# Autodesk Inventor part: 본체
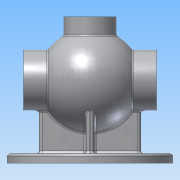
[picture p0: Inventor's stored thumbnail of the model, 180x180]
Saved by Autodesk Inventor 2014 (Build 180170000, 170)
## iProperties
Created: 2020-08
Part Number: 본체
Material: 알루미늄 6061
Document SubType Name: Modeling
Designer: kb542
Mass: 1759.43 g
Surface Area: 1343.08 cm^2
Volume: 649.236 cm^3
Density: 2.71 g/cm^3
Appearance: 알루미늄 - 평지
Author: kb542
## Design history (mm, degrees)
sketch "스케치1"
  geometry: L1 (-68, 0)-(68, 0); L2 (-68, 0)-(-68, 31); L3 (-68, 31)-(-42.988, 31); L4 (42.988, 31)-(68, 31); L5 (68, 31)-(68, 0); L6 (-52, 17.5)-(-52, 18.5); L7 (-52, 18.5)-(-50.25, 18.5); L8 (-50.25, 18.5)-(-50.25, 17.5); L9 (-50.25, 17.5)-(-39.278, 17.5); L10 (39.278, 17.5)-(68, 17.5); L11 (-52, 17.5)-(-68, 17.5); A1 r 43 centre (0, 0) between (39.278, 17.5) and (-39.278, 17.5); A2 r 53 centre (0, 0) between (42.988, 31) and (-42.988, 31); 2 further points
  constraints: 22 end point, 4 horizontal, 4 perpendicular, 4 point on circle, 3 coincident, 2 centre point, 2 point on line, 1 midpoint, 1 parallel, 1 vertical
  dimensions: "d0" = 136 distance of L1.start L1.end; "d1" = 62 diameter of L3 L1; "d2" = 62 diameter of L4 L1; "d8" = 35 diameter of L11 L1; "d9" = 37 diameter of L7 L1; "d10" = 1.75 distance of L6.end L7.end; "d11" = 35 diameter of L9 L1; "d12" = 43 radius of A1; "d13" = 35 diameter of L10 L1; "d14" = 16 distance of L6.start L11.end; "d16" = 53 radius of A2
revolve "회전1" sketch "스케치1" stored, may be unused: angle "d15" = 90 deg
chamfer "모따기1" distance "d17" = 1; stored, may be unused: second distance "d18" = 2, angle "d19" = 45 deg
sketch "스케치2"
  geometry: L1 (-27, 45.607)-(27, 45.607); L2 (-27, 45.607)-(27, 45.607); A1 r 53 centre (0, 0) between (-27, 45.607) and (27, 45.607) reference; A2 r 53 centre (0, 0) between (27, 45.607) and (-27, 45.607); 1 further point
  constraints: 4 end point, 4 point on circle, 2 horizontal, 1 centre point, 1 concentric
  dimensions: "d20" = 54 distance of L1.start L1.end; "d21" = 45.60702 distance from line of A2.centre L1
extrude "돌출1" cut sketch "스케치2" stored distance "d22" = 10; taper "d23" = 0 deg
sketch "스케치3"
  geometry: 2 further points
  constraints: 1 horizontal alignment
  dimensions: "d24" = 24 distance of point (0, 0) point (-24, 0)
hole "구멍1" sketch "스케치3" at (-24, 0) diameter "d25" = 3.242; stored, may be unused: countersink angle "d29" = 90 deg, drill point angle "d31" = 118 deg; dims "d26" = 12, "d27" = 4, "d28" = 2, "d30" = 15
sketch "스케치4"
  geometry: 2 further points
  constraints: 1 horizontal alignment
  dimensions: "d35" = 24 distance of point (0, 0) point (24, 0)
hole "구멍2" sketch "스케치4" at (24, 0) diameter "d36" = 3.242; stored, may be unused: countersink angle "d40" = 90 deg, drill point angle "d42" = 118 deg; dims "d37" = 12, "d38" = 4, "d39" = 2, "d41" = 15
node "작업 평면1"
sketch "스케치6"
  geometry: C1 r 85 at (0, 0); 1 further point
  constraints: 1 centre point, 1 coincident
  dimensions: "d47" = 170 diameter of C1
extrude "돌출2" join sketch "스케치6" distance "d48" = 10; taper "d49" = 0 deg
fillet "모깎기1" dims "d50" = 3
sketch "스케치7"
  geometry: A1 r 72.5 centre (0, 0) between (0, -72.5) and (72.5, 0); 3 further points
  constraints: 4 point on circle, 2 horizontal alignment, 2 vertical alignment, 1 centre point, 1 coincident
  dimensions: "d51" = 145 diameter of A1
hole "구멍3" sketch "스케치7" at (0, -72.5), (72.5, 0), (0, 72.5), (-72.5, 0) diameter "d52" = 9; stored, may be unused: countersink angle "d56" = 90 deg, drill point angle "d58" = 118 deg; dims "d53" = 12, "d54" = 4, "d55" = 2, "d57" = 15
sketch "스케치8"
  geometry: L1 (-82, -75)-(82, -75) reference; L2 (43, 0)-(43, -75); L3 (-43, 0)-(-43, -75); L4 (43, -75)-(-43, -75); A1 r 43 centre (0, 0) between (43, 0) and (-43, 0) reference; A2 r 43 centre (0, 0) between (-43, 0) and (43, 0); 1 further point
  constraints: 6 end point, 4 point on circle, 2 point on line, 1 centre point, 1 collinear, 1 concentric, 1 parallel, 1 perpendicular
  dimensions: "d59" = 43 distance from line of point (0, 0) L2; "d60" = 86 distance between parallel lines of L3 L2
extrude "돌출3" join sketch "스케치8" stored distance "d61" = 8; taper "d62" = 0 deg
sketch "스케치10"
  geometry: L1 (-68, -31)-(-42.988, -31) reference; L2 (42.988, -31)-(68, -31) reference; L3 (-82, -75)-(82, -75) reference; L4 (-52, -31)-(-52, -75); L5 (52, -31)-(52, -75); 1 further point
  constraints: 4 end point, 4 point on line, 2 perpendicular
  dimensions: "d63" = 52 distance from line of point (0, 0) L4; "d64" = 104 distance between parallel lines of L5 L4
feature "리브1" dims "d65" = 1, "d66" = 8, "d67" = 0, "d68" = 0, "d69" = 1, "d70" = 1
feature "리브2" dims "d71" = 1, "d72" = 8, "d73" = 0, "d74" = 0, "d75" = 1, "d76" = 1
fillet "모깎기2" dims "d77" = 3
fillet "모깎기3" dims "d78" = 3
fillet "모깎기4" dims "d79" = 3
fillet "모깎기5" dims "d80" = 3
node "작업 평면2"
sketch "스케치11"
  geometry: C1 r 27 at (0, 0); 1 further point
  constraints: 1 centre point, 1 coincident
  dimensions: "d82" = 54 diameter of C1
extrude "돌출4" join sketch "스케치11" stored distance "d83" = 8; taper "d84" = 0 deg
sketch "스케치12"
  geometry: C1 r 13 at (0, 0); 1 further point
  constraints: 1 centre point, 1 coincident
  dimensions: "d85" = 26 diameter of C1
extrude "돌출5" cut sketch "스케치12" stored distance "d86" = 8; taper "d87" = 0 deg
chamfer "모따기2" distance "d88" = 1; stored, may be unused: second distance "d89" = 2, angle "d90" = 45 deg
fillet "모깎기6" dims "d91" = 3
sketch "스케치13"
  geometry: 2 further points
  constraints: 1 vertical alignment
  dimensions: "d92" = 20 distance of point (0, 0) point (0, 20)
hole "구멍4" sketch "스케치13" at (0, 20) diameter "d93" = 3.242; stored, may be unused: countersink angle "d97" = 90 deg, drill point angle "d99" = 118 deg; dims "d94" = 12, "d95" = 4, "d96" = 2, "d98" = 15
node "작업 평면3"
node "작업 평면4"
sketch "스케치17"
  geometry: L1 (-27, 65)-(27, 65) reference; L2 (-27, 65)-(-27, 47.286) reference; 2 further points
  constraints: 1 other
  dimensions: "d109" = 9 distance from line of point (0, 56) L1; "d110" = 27 distance from line of point (0, 56) L2
feature "엠보싱2" sketch "스케치17" dims "d0" = 136, "d1" = 62, "d2" = 62, "d8" = 35, "d9" = 37, "d10" = 1.75, "d11" = 35, "d12" = 43, "d13" = 35, "d14" = 16, "d16" = 53, "d111" = 0.5, "d112" = 0
node "솔리드1"
pattern_circular "원형 패턴1" dims angle "d33" = 360 deg
pattern_circular "원형 패턴2" dims angle "d44" = 360 deg
pattern_circular "원형 패턴3" dims angle "d101" = 360 deg
other parameters: "d46" = -85
